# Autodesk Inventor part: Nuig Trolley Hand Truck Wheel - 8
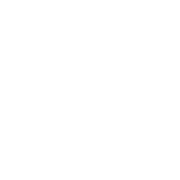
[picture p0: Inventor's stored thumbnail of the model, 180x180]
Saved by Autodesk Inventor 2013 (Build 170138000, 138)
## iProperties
Shininess: 64.0
Length Units: 11269
Angle Units: 11279
Time Units: 11290
Mass Units: 11286
Length Display Precision: 3
Angle Display Precision: 2
Compacted: True
Manager: Larry mc nice
Company: Nuig
Created: 2002-08
Part Number: Nuig Trolley Hand Truck Wheel - 8
Document SubType Name: Modeling
Designer: kalamea
Description: STANDARD ABS PLASTIC WHEEL
Mass: 824.979 g
Surface Area: 1249.4 cm^2
Volume: 824.979 cm^3
Density: 1 g/cm^3
Stock Number: 006aswe
Material: Generic
Density: 0.0
Volumn: 0.0
Area: 0.0
PropertySet Name: Model Information
Control State: 0
Master: False
Checked Out: False
DRAWING NUMBER: ME07-2007-PT
Title: MR WHEEL
Author: kalamea
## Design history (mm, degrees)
sketch "Sketch1"
  geometry: L1 (-25.4, 9.525)-(25.4, 9.525); L2 (25.4, 9.525)-(25.4, 19.05); L3 (25.4, 19.05)-(6.35, 24.765); L4 (6.35, 24.765)-(6.35, 82.55); L5 (6.35, 82.55)-(25.4, 82.55); L6 (25.4, 82.55)-(25.4, 98.374); L7 (-25.4, 9.525)-(-25.4, 19.05); L8 (-25.4, 19.05)-(-6.35, 24.765); L9 (-6.35, 24.765)-(-6.35, 82.55); L10 (-6.35, 82.55)-(-25.4, 82.55); L11 (-25.4, 82.55)-(-25.4, 98.374); L12 (0, 9.525)-(0, 101.6); L13 (-65.696, 0)-(65.696, 0); A1 r 2 centre (-21.295, 99.343) between (-23.245, 98.901) and (-19.344, 99.785); A2 r 2 centre (21.295, 99.343) between (19.327, 99.701) and (23.247, 98.909); A3 r 101.653 centre (-0.21, 0) between (25.4, 98.374) and (23.247, 98.909); A4 r 101.547 centre (-0.21, 0) between (-23.245, 98.901) and (-25.4, 98.374); A5 r 2 centre (-9.519, 101.153) between (-11.511, 100.972) and (-7.528, 101.336); A6 r 2 centre (9.519, 101.153) between (7.525, 101.305) and (11.506, 100.92); A7 r 101.597 centre (-0.21, 0) between (19.327, 99.701) and (11.506, 100.92); A8 r 101.6 centre (-0.21, 0) between (7.525, 101.305) and (-7.528, 101.336); A9 r 101.603 centre (-0.21, 0) between (-11.511, 100.972) and (-19.344, 99.785); 3 further points
  constraints: 26 end point, 19 point on circle, 9 centre point, 6 parallel, 5 collinear, 4 midpoint, 3 perpendicular, 2 symmetric about line, 1 coincident, 1 equal radius, 1 horizontal, 1 vertical alignment, 2 other
  dimensions: "d0" = 50.8 distance of L1.end L1.start; "d1" = 19.05 diameter of L1.end L13; "d2" = 38.1 diameter of L2.end L13; "d3" = 203.2 diameter of L12.end L13; "d4" = 165.1 diameter of L10 L13; "d5" = 19.05 horizontal distance of L8.end L1.start; "d6" = 19.05 horizontal distance of L1.end L3.end; "d8" = 15.24 vertical distance of L8.end L1.start; "d9" = 15.24 vertical distance of L1.end L3.end; "d10" = 38.1 diameter of L7.end L13; "d14" = 2 radius of A1
revolve "Revolution1" sketch "Sketch1" stored, may be unused: angle "d11" = 90 deg
sketch "Sketch2"
  geometry: C1 r 1.84 at (11.255, 8.529)
  constraints: 1 centre point
extrude "Extrusion1" cut sketch "Sketch2" distance "d12" = 10; taper "d13" = 0 deg
body "Solid1"
other parameters: "d7" = 101.6
